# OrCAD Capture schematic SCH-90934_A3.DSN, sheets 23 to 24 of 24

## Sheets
23 C-16 IO EXPI/Miscs: size A2
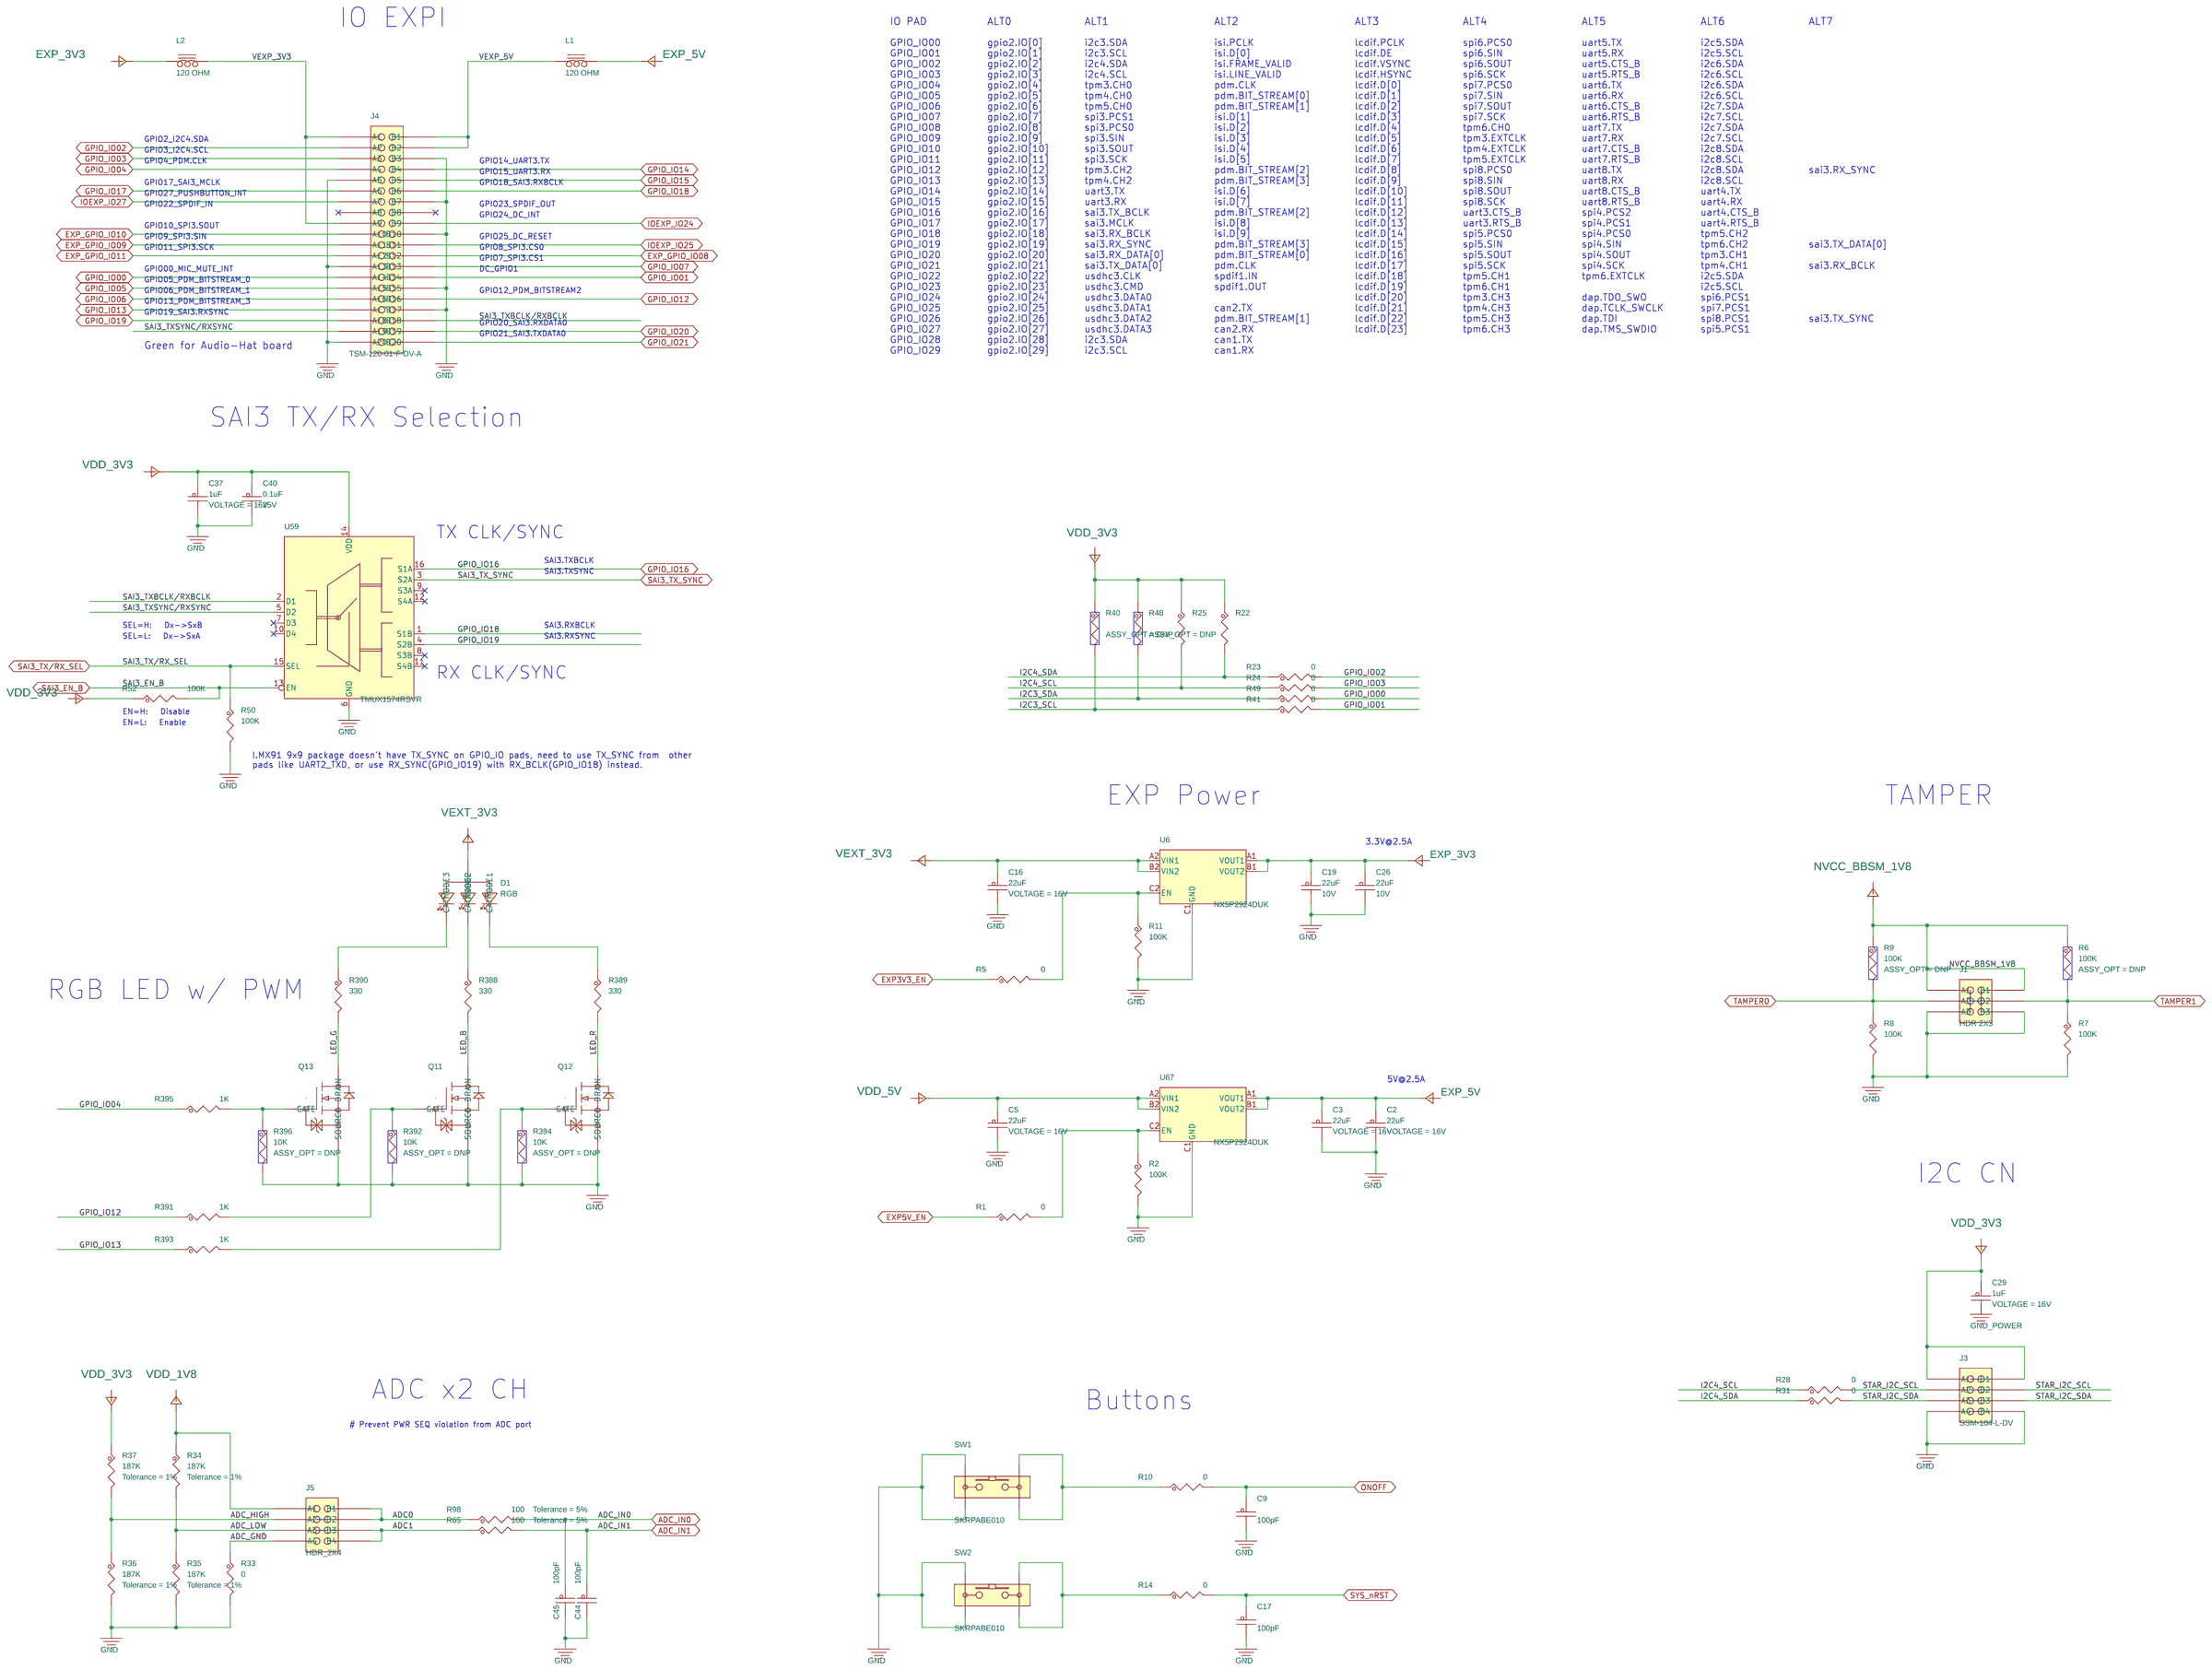
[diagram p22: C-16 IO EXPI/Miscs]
24 C-08 eMMC/MicroSD/QSPI: size C
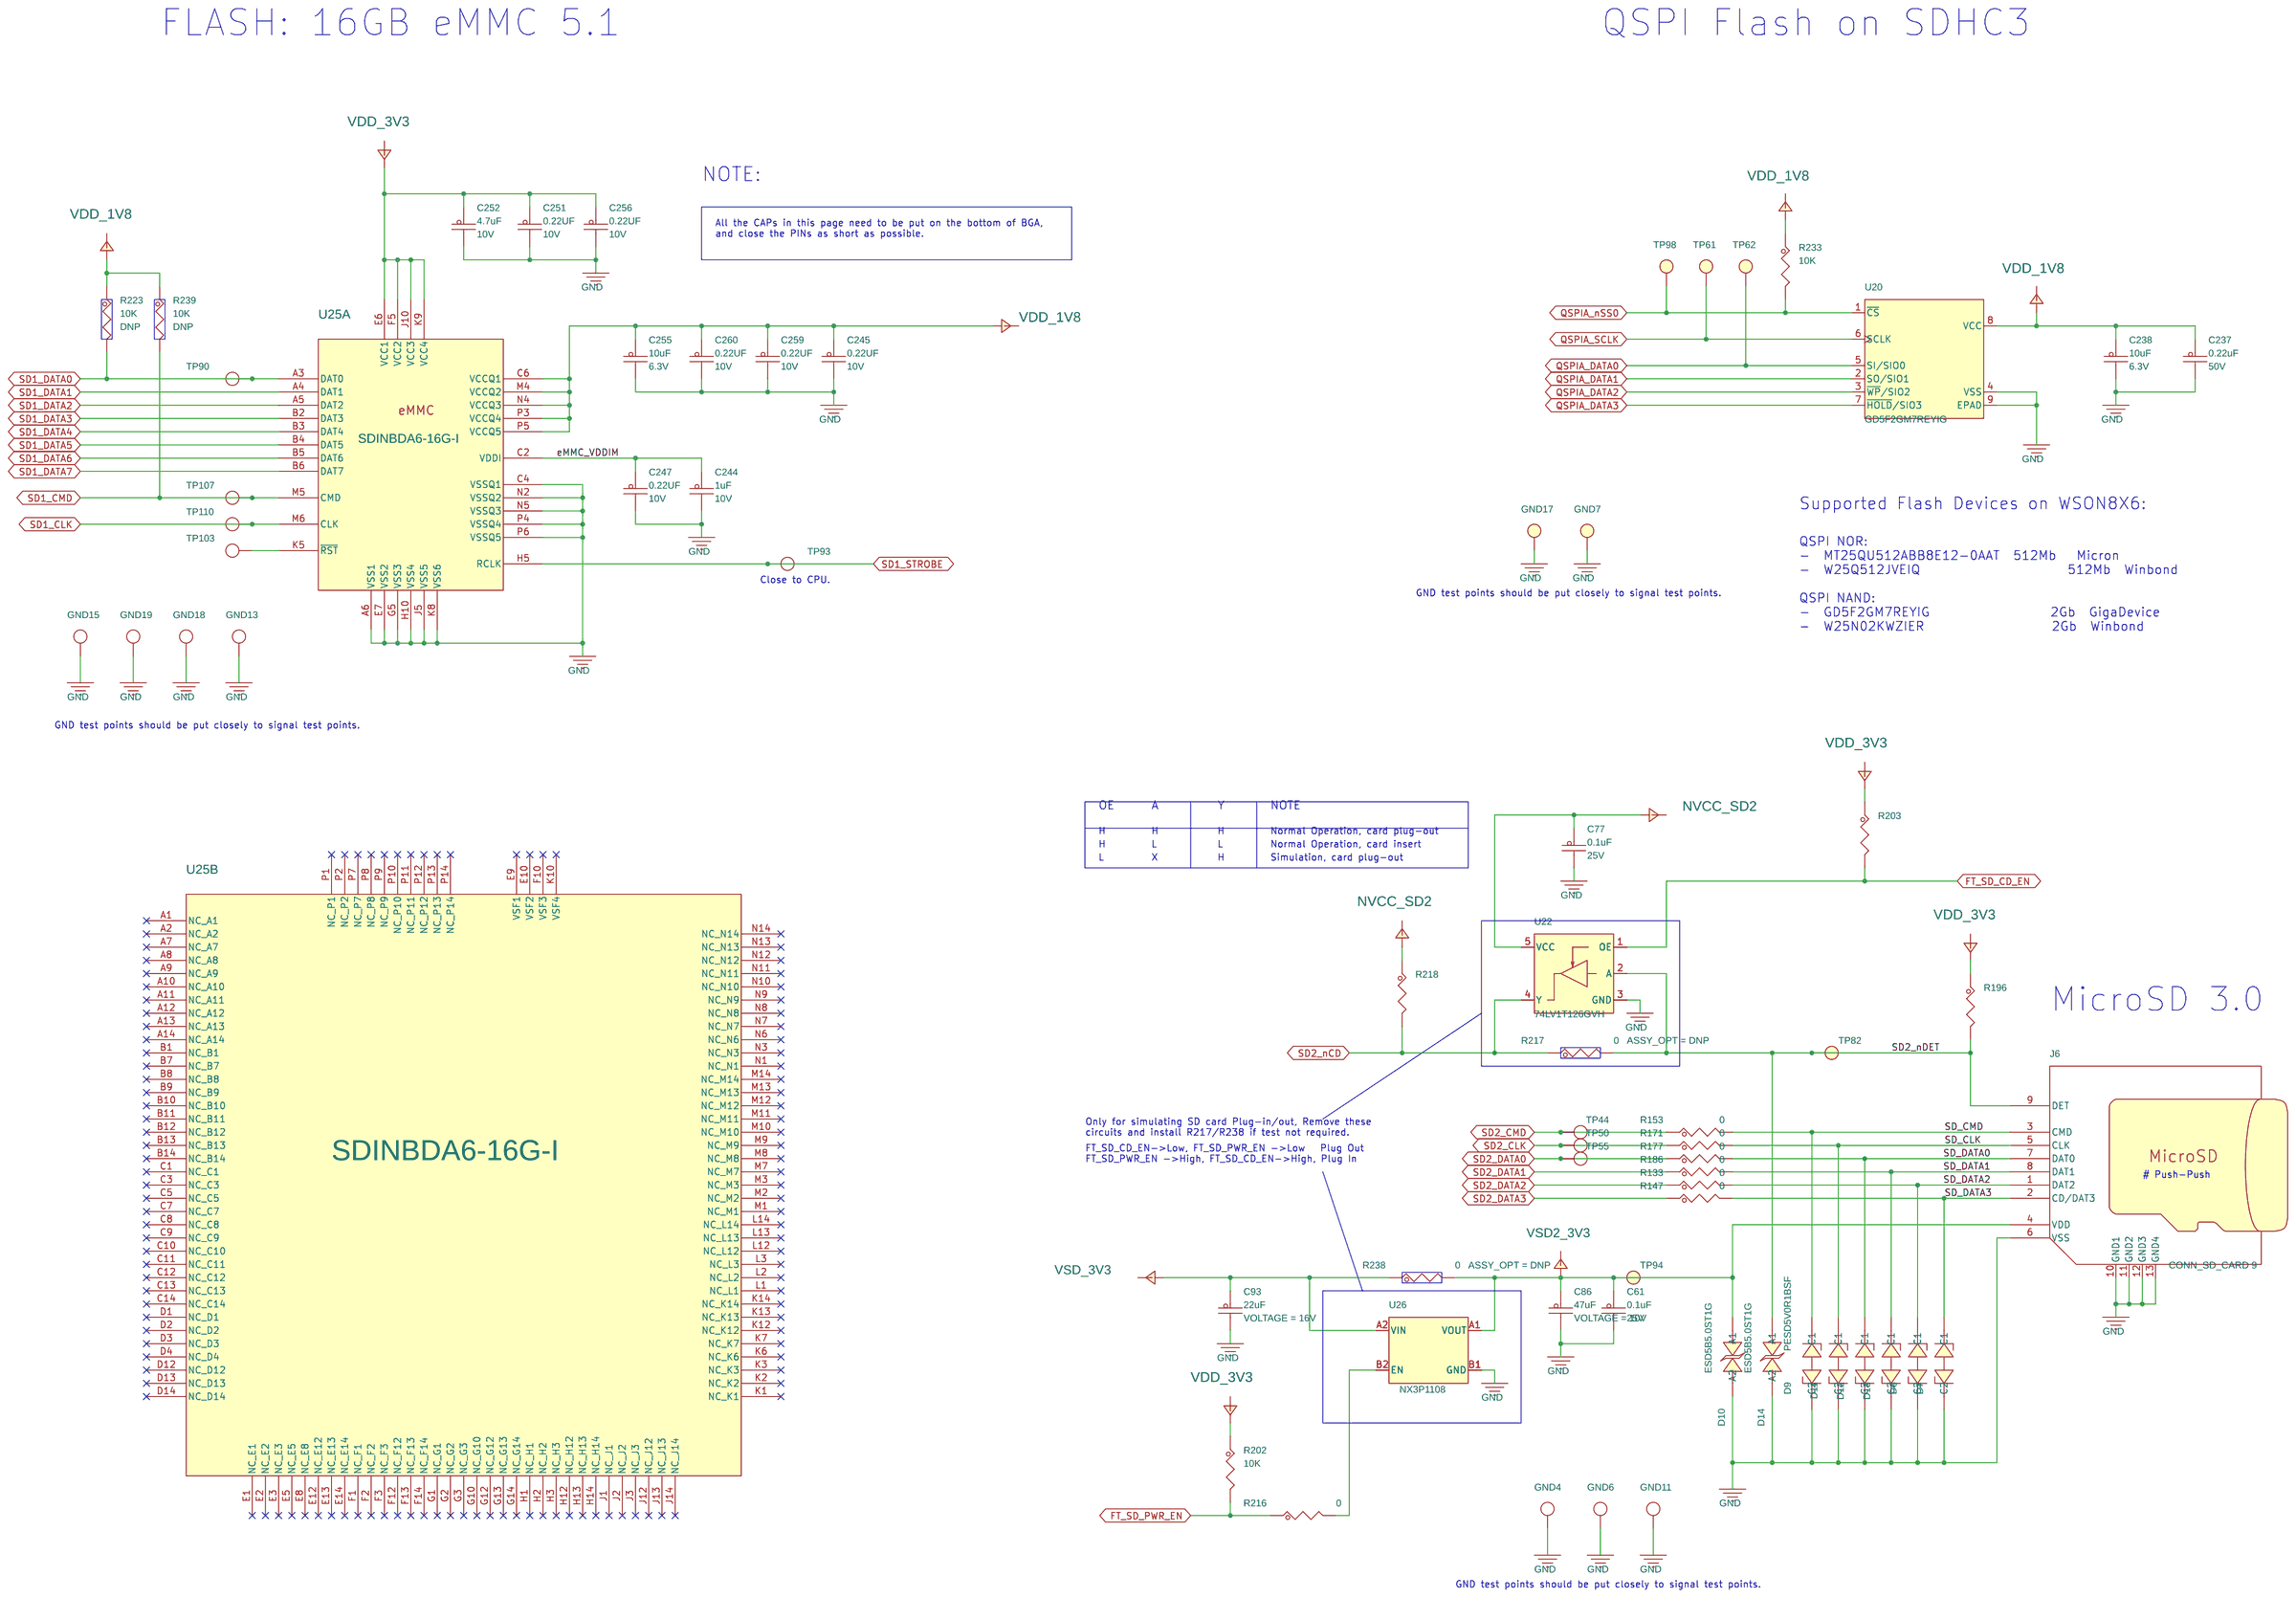
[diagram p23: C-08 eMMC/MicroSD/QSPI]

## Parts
sheet C-08 eMMC/MicroSD/QSPI
C61  0.1uF  [CC0402_25]
C77  0.1uF  [CC0402_25]
C86  47uF  [0805_CC]
C93  22uF  [CC0805_OV]
C237  0.22uF  [CC0402_25]
C238  10uF  [0402_cc_nsp]
C244  1uF  [0201_CC]
C245  0.22UF  [0201_CC]
C247  0.22UF  [0201_CC]
C251  0.22UF  [0201_CC]
C252  4.7uF  [cc0402_tol0p15]
C255  10uF  [0402_cc_nsp]
C256  0.22UF  [0201_CC]
C259  0.22UF  [0201_CC]
C260  0.22UF  [0201_CC]
D6  PESD5V0R1BSF  [dsn0603-2]
D7  PESD5V0R1BSF  [dsn0603-2]
D9  PESD5V0R1BSF  [dsn0603-2]
D10  ESD5B5.0ST1G  [diode2_sod523]
D11  PESD5V0R1BSF  [dsn0603-2]
D12  PESD5V0R1BSF  [dsn0603-2]
D13  PESD5V0R1BSF  [dsn0603-2]
D14  ESD5B5.0ST1G  [diode2_sod523]
GND4  TPAD_020  [tpad_020]
GND6  TPAD_020  [tpad_020]
GND7  TP_35MIL  [testpoint_35mil]
GND11  TPAD_020  [tpad_020]
GND13  TPAD_020  [tpad_020]
GND15  TPAD_020  [tpad_020]
GND17  TP_35MIL  [testpoint_35mil]
GND18  TPAD_020  [tpad_020]
GND19  TPAD_020  [tpad_020]
J6  CONN_SD_CARD 9  [con9_sdcard_1p1mm]
R133  0  [0402_CC]
R147  0  [0402_CC]
R153  0  [0402_CC]
R171  0  [0402_CC]
R177  0  [0402_CC]
R186  0  [0402_CC]
R196  10K  [0402_CC]
R202  10K  [0402_CC]
R203  10K  [0402_CC]
R216  0  [0402_CC]
R217  0  [0402_CC]
R218  10K  [0402_CC]
R223  10K  [0402_CC]
R233  10K  [0402_CC]
R238  0  [0402_CC]
R239  10K  [0402_CC]
TP44  TPAD_020  [tpad_020]
TP50  TPAD_020  [tpad_020]
TP55  TPAD_020  [tpad_020]
TP61  TP_35MIL  [testpoint_35mil]
TP62  TP_35MIL  [testpoint_35mil]
TP82  TP_35MIL  [testpoint_35mil]
TP90  TPAD_020  [tpad_020]
TP93  TPAD_020  [tpad_020]
TP94  TP_35MIL  [testpoint_35mil]
TP98  TP_35MIL  [testpoint_35mil]
TP103  TPAD_015  [TPAD_015]
TP107  TPAD_020  [tpad_020]
TP110  TPAD_020  [tpad_020]
U20  GD5F2GM7REYIG  [wson8_1p27_8x6mm_ep136x171]
U22  74LV1T126GVH  [sot753_5p_1p7x3p1mm]
U25  SDINBDA6-16G-I  [fbga153_0p5_11p5x13]  (sections A,B)
U26  NX3P1108  [wlcsp4_0p5_0p99x0P99]
sheet C-16 IO EXPI/Miscs
C2  22uF  [CC0805_OV]
C3  22uF  [CC0805_OV]
C5  22uF  [CC0805_OV]
C9  100pF  [CC0402_25]
C16  22uF  [CC0805_OV]
C17  100pF  [CC0402_25]
C19  22uF  [CC0603]
C26  22uF  [CC0603]
C29  1uF  [CC0402_25]
C37  1uF  [CC0402_25]
C40  0.1uF  [CC0402_25]
C44  100pF  [CC0402_25]
C45  100pF  [CC0402_25]
D1  RGB  [led4_3p4x3_sm]
J1  HDR 2X3  [hdr203_tmm_210h]
J3  SSM-104-L-DV  [con_2x4_skt_100_sm]
J4  TSM-120-01-F-DV-A  [hdr220_tsm_a_sm]
J5  HDR_2X4  [HDR204_TMM_SM]
L1  120 OHM  [IND_0603]
L2  120 OHM  [IND_0603]
Q11  NX3008NBKW,115  [sc70_3]
Q12  NX3008NBKW,115  [sc70_3]
Q13  NX3008NBKW,115  [sc70_3]
R1  0  [0402_CC]
R2  100K  [0402_CC]
R5  0  [0402_CC]
R6  100K  [0402_CC]
R7  100K  [0402_CC]
R8  100K  [0402_CC]
R9  100K  [0402_CC]
R10  0  [0402_CC]
R11  100K  [0402_CC]
R14  0  [0402_CC]
R22  2.2K  [0402_CC]
R23  0  [0402_CC]
R24  0  [0402_CC]
R25  2.2K  [0402_CC]
R28  0  [0402_CC]
R31  0  [0402_CC]
R33  0  [0402_CC]
R34  187K  [0402_CC]
R35  187K  [0402_CC]
R36  187K  [0402_CC]
R37  187K  [0402_CC]
R40  2.2K  [0402_CC]
R41  0  [0402_CC]
R48  2.2K  [0402_CC]
R49  0  [0402_CC]
R50  100K  [0402_CC]
R52  100K  [0402_CC]
R65  100  [RC0402_25]
R98  100  [RC0402_25]
R388  330  [RC0402_25]
R389  330  [RC0402_25]
R390  330  [RC0402_25]
R391  1K  [0402_CC]
R392  10K  [0402_CC]
R393  1K  [0402_CC]
R394  10K  [0402_CC]
R395  1K  [0402_CC]
R396  10K  [0402_CC]
SW1  SKRPABE010  [sw4_skrp]
SW2  SKRPABE010  [sw4_skrp]
U6  NX5P2924DUK  [wlcsp6_0p5_0p89x1p39]
U59  TMUX1574RSVR  [pqfn16_0p4_2p65x1p85]
U67  NX5P2924DUK  [wlcsp6_0p5_0p89x1p39]

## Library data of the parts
C40 C61 C77 = CAP_NP: CAP CER 0.1UF 25V 10% X5R 0402; AGILE_PN: 150-78633; CAD_APPROVED: Yes; FPLIST: CC0402_25,CC0402_HD,0402_CC,capc0402_l; HEIGHT: 0.55MM; MFG_NAME01: YAGEO AMERICA; MFG_PN01: CC0402KRX5R8BB104; Package Size: 0402; ROHS: Yes; Rated Voltage: 25V; Temp Range: -55C to +85C; Tolerance: 10%; VOLTAGE: 25V
C86 = CAP_NP: CAP CER 47uF 10V 20% X5R 0805; AGILE_PN: 150-78979; CAD_APPROVED: Yes; FPLIST: CC0805_OV,CC0805,0805_CC; HEIGHT: 1.45 MM; MFG_NAME01: TDK; MFG_PN01: C2012X5R1A476M125AC; ROHS: Yes; Rated Voltage: 10V; Temp Range: -55C to +85C; Tolerance: 20%; VOLTAGE: 10V
C2 C3 C5 C16 C93 = CAP_NP: CAP CER 22UF 16V 20% X5R 0805; 3D_Mechanical_Footprint_File: http://fcl.am.freescale.net/ALLEGRO/step/cc0805_ov.STEP; AGILE_PN: 150-81221; CAD_APPROVED: Yes; FPLIST: CC0805_OV,CC0805,0805_CC; HEIGHT: 1.45MM; MFG_NAME01: TDK Corporation; MFG_PN01: C2012X5R1C226M125AC; Package Size: 0805 (2012 Metric); ROHS: Yes; Rated Voltage: 16V; Temp Range: -55C to +85C; Tolerance: 20%; VOLTAGE: 16V
C237 = CAP_NP: CAP CER 0.22uF 50V 10% X5R 0402; AGILE_PN: 150-79999; CAD_APPROVED: Yes; FPLIST: CC0402_25,CC0402_HD,0402_CC; HEIGHT: 0.55MM; MFG_NAME01: TAIYO YUDEN; MFG_PN01: UMK105BJ224KV-F; Package Size: 0402; ROHS: Yes; Rated Voltage: 50V; Temp Range: -55C to +85C; Temp_Range: -55°C to +85°C; Tolerance: 10%; VOLTAGE: 50V
C238 C255 = CAP_NP: CAP CER 10UF 6.3V 20% X5R 0402; 3D_Mechanical_Footprint_File: cc0402_tol0p2; AGILE_PN: 150-79163; CAD_APPROVED: Yes; FPLIST: CC0402_25,CC0402_HD,0402_CC; HEIGHT: 0.7 MM; MFG_NAME01: SAMSUNG ELECTRO MECHANICS; MFG_PN01: CL05A106MQ5NUNC; ROHS: Yes; Rated Voltage: 6.3V; Temp Range: -55C to +85C; Tolerance: 20%; VOLTAGE: 6.3V
C244 = CAP_NP: CAP CER 1.0uF 10V 10% X5R 0201; AGILE_PN: 150-81088; CAD_APPROVED: Yes; FPLIST: CC0201,CC0201_HD,0201_CC,cc_0201_cir; HEIGHT: 0.35MM; MFG_NAME01: SAMSUNG ELECTRO MECHANICS; MFG_PN01: CL03A105KP3NSNC; Package Size: 0201 (0603 Metric); Package Type: SMD/SMT; ROHS: Yes; Rated Voltage: 10V; Temp Range: -55C to +85C; Tolerance: 10%; VOLTAGE: 10V
C245 C247 C251 C256 C259 C260 = CAP_NP: CAP CER 0.22UF 10V 20% X5R 0201; 3D_Mechanical_Footprint_File: http://fcl.am.freescale.net/ALLEGRO/step/cc0201.STEP; AGILE_PN: 150-78815; CAD_APPROVED: Yes; FPLIST: CC0201,CC0201_HD,0201_CC; HEIGHT: 0.33MM; MFG_NAME01: KYOCERA; MFG_PN01: 0201ZD224MAT2A; Package Size: 0201; ROHS: Yes; Rated Voltage: 10V; Temp Range: -55C to +85C; Tolerance: 20%; VOLTAGE: 10V
C252 = CAP_NP: CAP CER 4.7uF 10V 10% X5R 0402; AGILE_PN: 150-80044; CAD_APPROVED: Yes; FPLIST: cc0402_tol0p15,cc0402_tol0p15_ov,0402_cc_nsp; HEIGHT: 0.65MM; MFG_NAME01: SAMSUNG ELECTRO MECHANICS; MFG_PN01: CL05A475KP5NRNC; ROHS: Yes; Rated Voltage: 10V; Temp Range: -55C to +85C; Tolerance: 10%; VOLTAGE: 10V
D6 D7 D9 D11-D13 = DIODE_BIDIR: DIODE TVS 5VWM 9.2VC DSN0603-2; 3D_Mechanical_Footprint_File: http://fcl.am.freescale.net/ALLEGRO/step/dsn0603-2.STEP; AGILE_PN: 480-79664; CAD_APPROVED: Yes; HEIGHT: 0.32; MFG_NAME01: NEXPERIA; MFG_PN01: PESD5V0R1BSFYL
D10 D14 = DIODE_TVS_BIDIR: DIODE SUPPRESSOR 16A@30NS 5V@1UA SOD-523; 3D_Mechanical_Footprint_File: http://fcl.am.freescale.net/ALLEGRO/step/diode2_sod523.STEP; AGILE_PN: 480-76937; CAD_APPROVED: Yes; HEIGHT: 0.7; MFG_NAME01: ON SEMICONDUCTOR
GND4 GND6 GND11 GND13 GND15 GND18 GND19 TP44 TP50 TP55 TP90 TP93 TP107 TP110 = TESTLOOP: TEST POINT PAD 0.5MM DIA SMT, NO PART TO ORDER; AGILE_PN: 211-77484; ASSY_OPT: DNP; CAD_APPROVED: Yes; HEIGHT: 0.1MM; ROHS: Yes
GND7 GND17 TP61 TP62 TP82 TP94 TP98 = T_POINT_R: TEST POINT PAD .035 SMT, no part to order; AGILE_PN: 510-75618; ASSY_OPT: DNP; CAD_APPROVED: Yes; HEIGHT: 0.1MM; ROHS: Yes
J6 = CONN_MICRO_SDCARD: CON 9 SD CARD PUSH SMT 1.1MM SP 81H AU; AGILE_PN: 211-79878; CAD_APPROVED: Yes; HEIGHT: 2.05; MFG_NAME01: SHENZHEN ATOM TECHNOLOGY CO.,LTD; MFG_PN01: MR01A-01202; Package Type: SMT; ROHS: Yes
R1 R5 R10 R14 R23 R24 R28 R31 R33 R41 R49 R133 R147 R153 R171 R177 R186 R216 = RES: RES MF ZERO OHM 1/16W 5% 0402; AGILE_PN: 470-75394; CAD_APPROVED: Yes; FPLIST: RC0402_25,RC0402_HD,RC0402_X2,0402_CC; HEIGHT: 0.45; MFG_NAME01: YAGEO AMERICA; MFG_PN01: RC0402JR-070RL; ROHS: Yes; Temp Range: -55 to +155C; Tolerance: 5%; VOLTAGE: 1/16W
R196 R202 R203 R218 R233 = RES: RES MF 10K 1/16W 5% 0402; AGILE_PN: 470-75557; CAD_APPROVED: Yes; FPLIST: RC0402_25,RC0402_HD,0402_CC; HEIGHT: 0.4 MM; MFG_NAME01: VISHAY INTERTECHNOLOGY; MFG_PN01: CRCW040210K0JNED; ROHS: Yes; Tolerance: 5%
R217 R238 = RES: RES MF ZERO OHM 1/16W 5% 0402; AGILE_PN: 470-75394; ASSY_OPT: DNP; CAD_APPROVED: Yes; FPLIST: RC0402_25,RC0402_HD,RC0402_X2,0402_CC; HEIGHT: 0.45; MFG_NAME01: YAGEO AMERICA; MFG_PN01: RC0402JR-070RL; ROHS: Yes; Temp Range: -55 to +155C; Tolerance: 5%; VOLTAGE: 1/16W
R223 R239 R392 R394 R396 = RES: RES MF 10K 1/16W 5% 0402; AGILE_PN: 470-75557; ASSY_OPT: DNP; CAD_APPROVED: Yes; FPLIST: RC0402_25,RC0402_HD,0402_CC; HEIGHT: 0.4 MM; MFG_NAME01: VISHAY INTERTECHNOLOGY; MFG_PN01: CRCW040210K0JNED; ROHS: Yes; Tolerance: 5%
TP103 = TESTLOOP: TEST POINT PAD 15MIL DIA SMT, NO PART TO ORDER; AGILE_PN: 211-76645; ASSY_OPT: DNP; CAD_APPROVED: Yes; HEIGHT: 0.1MM; MFG_NAME01: NOTACOMPONENT; MFG_PN01: NOTACOMPONENT; ROHS: Yes
U20 = GD5F1GQ4RCYIG_WSON8: IC SPI NAND FLASH QUAD 2Gb 104MHz 1.7-2V WSON8; 3D_Mechanical_Footprint_File: http://fcl.am.freescale.net/ALLEGRO/step/wson8_1p27_8x6mm_ep136x171.step; AGILE_PN: 342-82716; CAD_APPROVED: Yes; HEIGHT: 0.85; MFG_NAME01: GIGA DEVICE SEMICONDUCTOR INC.; ROHS: Yes; Temp Range: -40C to +85C; VOLTAGE: 1.7-2V
U22 = 74LV1T126GVH: IC VXLTR 1BIT BUF DRV 1.6-5.5V SOT753; 3D_Mechanical_Footprint_File: http://fcl.am.freescale.net/ALLEGRO/step/sot753_5p_1p7x3p1mm.STEP; AGILE_PN: 312-83148; CAD_APPROVED: Yes; HEIGHT: 1.1; MFG_NAME01: Nexperia; Package Size: SC-74A-5; ROHS: Yes; Temp Range: -40°C to +125°C; VOLTAGE: 1.6-5.5V
U25 = SDINBDA6_32G_I_VFBGA_153P: IC MEM NAND FLASH 16GB MMC 5.1 CTLR 2.7-3.6V FBGA153; 3D_Mechanical_Footprint_File: http://fcl.am.freescale.net/ALLEGRO/step/fbga153_0p5_11p5x13.STEP; AGILE_PN: 342-00870; CAD_APPROVED: Yes; HEIGHT: 1; MFG_NAME01: SANDISK CORPORATION; ROHS: Yes; Temp Range: -25°C to 85°C
U26 = NX3P1108_4P: IC LOAD SW 1.5A 0.9-3.6V WLCSP4; 3D_Mechanical_Footprint_File: http://fcl.am.freescale.net/ALLEGRO/step/wlcsp4_0p5_0p99x0P99.STEP; AGILE_PN: 315-81596; CAD_APPROVED: Yes; HEIGHT: 0.59; MFG_NAME01: NXP SEMICONDUCTOR; MFG_PN01: NX3P1108UKZ; ROHS: Yes; Temp Range: -40C to +85C; VOLTAGE: 0.9-3.6V
C9 C17 C44 C45 = CAP_NP: CAP CER 100PF 50V 5% C0G 0402; AGILE_PN: 150-79170; CAD_APPROVED: Yes; FPLIST: CC0402_25,CC0402_HD,0402_CC,capc0402_l; HEIGHT: 0.55MM; MFG_NAME01: AVX; MFG_PN01: 04025A101JAT2A; ROHS: Yes; Rated Voltage: 50V; Temp Range: -55C to +125C; Tolerance: 5%; VOLTAGE: 50V
C19 C26 = CAP_NP: CAP CER 22uF 10V 20% X5R 0603; AGILE_PN: 150-79530; CAD_APPROVED: Yes; FPLIST: CC0603_OV,CC0603,0603_cc_tol; HEIGHT: 1MM; MFG_NAME01: SAMSUNG; MFG_PN01: CL10A226MP7LUNC; Package Size: 0603; ROHS: Yes; Rated Voltage: 10V; SIGNAL_MODEL: DEFAULT_CAPACITOR_2.2e+07pF_2_1; Temp Range: -55C to +85C; Tolerance: 20%; VOLTAGE: 10V; WVDC: 6.3V
C29 C37 = CAP_NP: CAP CER 1uF 16V 10% X5R 0402; AGILE_PN: 150-78973; CAD_APPROVED: Yes; FPLIST: CC0402_25,CC0402_HD,0402_CC,capc0402_l; HEIGHT: 0.55 MM; MFG_NAME01: TDK; MFG_PN01: C1005X5R1C105K; ROHS: Yes; Rated Voltage: 16V; SIGNAL_MODEL: DEFAULT_CAPACITOR_1e+06pF_2_1; TOL: 10%; Temp Range: -55C to +85C; Tolerance: 10%; VOLTAGE: 16V; voltage rating: 16V
D1 = LED_GPLY6900: LED RGB MULTI 20MA SMT; AGILE_PN: 370-76731; CAD_APPROVED: Yes; HEIGHT: 2.04; MFG_NAME01: EVERLIGHT INTERNATIONAL CORPORATION; MFG_PN01: 67-03A/R6GHBHW-A01/2T/MS; Rated Voltage: 1.7-3.7V; VOLTAGE: 1.7-3.7V
J1 = CONN_HDR_3X2: HDR 2X3 TH 2MM CTR 217H AU 110L; 3D_Mechanical_Footprint_File: http://fcl.am.freescale.net/ALLEGRO/step/hdr203_tmm_210h.STEP; AGILE_PN: 210-77094; CAD_APPROVED: Yes; FPLIST: hdr203_tmm_210h,hdr203_tmm; HEIGHT: 5.33; MFG_NAME01: SAMTEC; MFG_PN01: TMM-103-02-G-D; ROHS: Yes
J3 = CONN_HDR_4X2: CON 2X4 SKT SMT 2.54MM CTR 300H AU; 3D_Mechanical_Footprint_File: http://fcl.am.freescale.net/ALLEGRO/step/con_2x4_skt_100_sm.STEP; AGILE_PN: 211-79467; CAD_APPROVED: Yes; HEIGHT: 7.62; MFG_NAME01: SAMTEC; ROHS: Yes
J4 = CONN_HDR_20X2: HDR 2X20 SMT 2.54MM CTR 395H AU; 3D_Mechanical_Footprint_File: http://fcl.am.freescale.net/ALLEGRO/step/hdr220_tsm_a_sm.step; AGILE_PN: 211-80156; CAD_APPROVED: Yes; HEIGHT: 10.03; MFG_NAME01: SAMTEC; ROHS: Yes; Temp Range: -55°C ~ 125°C
J5 = CONN_HDR_4X2: HDR 2X4 SMT 78.7MIL CTR 235H AU LOPRO; 3D_Mechanical_Footprint_File: http://fcl.am.freescale.net/ALLEGRO/step/hdr204_tmm_sm.STEP; AGILE_PN: 211-75114; CAD_APPROVED: Yes; HEIGHT: 5.97; MFG_NAME01: SAMTEC; MFG_PN01: TMM-104-01-S-D-SM; Package Size: SMD-8; Package Type: SMD; ROHS: Yes; Temp Range: -55°C to +125°C
L1 L2 = BEAD_0: IND FER BEAD 120OHM@100MHZ 2A 25% 0603; AGILE_PN: 180-78419; CAD_APPROVED: Yes; FPLIST: IND_0603,0603_CC; HEIGHT: 0.95; MFG_NAME01: MURATA; MFG_PN01: BLM18PG121SN1D; ROHS: Yes
Q11-Q13 = NX3008NBKW_SOT323: TRAN NMOS SW 30V 350mA AEC-Q101 SC-70; 3D_Mechanical_Footprint_File: http://fcl.am.freescale.net/ALLEGRO/step/sc70_3.STEP; AGILE_PN: 480-79736; CAD_APPROVED: Yes; HEIGHT: 1.1; MFG_NAME01: NEXPERIA; ROHS: Yes
R2 R7 R8 R11 R50 R52 = RES: RES MF 100K 1/16W 5% 0402; AGILE_PN: 470-75597; CAD_APPROVED: Yes; FPLIST: RC0402_25,RC0402_HD,0402_CC; HEIGHT: 0.40 MM; MFG_NAME01: VENKEL COMPANY; MFG_PN01: CR0402-16W-104JT; ROHS: Yes; Temp Range: -55C to +155C; Temp_Range: -55C to +155C; Tolerance: 5%; VOLTAGE: 50V
R6 R9 = RES: RES MF 100K 1/16W 5% 0402; AGILE_PN: 470-75597; ASSY_OPT: DNP; CAD_APPROVED: Yes; FPLIST: RC0402_25,RC0402_HD,0402_CC; HEIGHT: 0.40 MM; MFG_NAME01: VENKEL COMPANY; MFG_PN01: CR0402-16W-104JT; ROHS: Yes; Temp Range: -55C to +155C; Temp_Range: -55C to +155C; Tolerance: 5%; VOLTAGE: 50V
R22 R25 = RES: RES MF 2.2K 1/16W 5% 0402; AGILE_PN: 470-76602; CAD_APPROVED: Yes; FPLIST: RC0402_25,RC0402_HD,0402_CC; HEIGHT: 0.4 MM; MFG_NAME01: YAGEO AMERICA; MFG_PN01: RC0402JR-072K2L; RATING: 1/16W; ROHS: Yes; Tolerance: 5%
R34-R37 = RES: RES MF 187K 1/16W 1% 0402; AGILE_PN: 470-31090; CAD_APPROVED: Yes; FPLIST: RC0402_25,RC0402_HD,0402_CC; HEIGHT: 0.40 MM; MFG_NAME01: WALSIN TECHNOLOGY CORP.; MFG_PN01: WR04X1873FTL; ROHS: Yes; Temp Range: -55C to +155C; Temp_Range: -55C to +155C; Tolerance: 1%; VOLTAGE: 50V
R40 R48 = RES: RES MF 2.2K 1/16W 5% 0402; AGILE_PN: 470-76602; ASSY_OPT: DNP; CAD_APPROVED: Yes; FPLIST: RC0402_25,RC0402_HD,0402_CC; HEIGHT: 0.4 MM; MFG_NAME01: YAGEO AMERICA; MFG_PN01: RC0402JR-072K2L; RATING: 1/16W; ROHS: Yes; Tolerance: 5%
R65 R98 = RES: RES MF 100 OHM 1/16W 5% 0402; AGILE_PN: 470-82142; CAD_APPROVED: Yes; FPLIST: RC0402_25,RC0402_HD,RC0402_X2,0402_CC; HEIGHT: 0.45MM; MFG_NAME01: SMEC; MFG_PN01: RC73L2Z101JTF; ROHS: Yes; Temp Range: -55°C to +175°C; Tolerance: 5%
R388-R390 = RES: RES MF 330 OHM 1/16W 5% 0402; AGILE_PN: 470-82124; CAD_APPROVED: Yes; FPLIST: RC0402_25,RC0402_HD,0402_CC; HEIGHT: 0.4MM; MFG_NAME01: NIC COMPONENTS CORP; MFG_PN01: NRCL04J331TRF; ROHS: Yes; Temp Range: -55 ~ +155; Tolerance: 5%
R391 R393 R395 = RES: RES MF 1.0K 1/16W 5% 0402; AGILE_PN: 470-75555; CAD_APPROVED: Yes; FPLIST: RC0402_25,RC0402_HD,RC0402_X2,0402_CC,CAPC0402_L; HEIGHT: 0.41mm; MFG_NAME01: VISHAY INTERTECHNOLOGY; MFG_PN01: CRCW04021K00JNED; ROHS: Yes; Tolerance: 5%
SW1 SW2 = SW_TC_SPST_4P: SW SPST PB SMT 16V 20MA; 3D_Mechanical_Footprint_File: http://fcl.am.freescale.net/ALLEGRO/step/sw4_skrp.step; AGILE_PN: 510-75638; CAD_APPROVED: Yes; HEIGHT: 2.5MM; MFG_NAME01: ALPS ELECTRIC (USA) INC.; ROHS: Yes
U6 U67 = NX5P2924DUK_WLCSP6: IC PWR SW LOGIC CONTROLED 0.8-5.5V 2.5A WLCSP6; 3D_Mechanical_Footprint_File: http://fcl.am.freescale.net/ALLEGRO/step/wlcsp6_0p5_0p89x1p39.STEP; AGILE_PN: 315-83992; CAD_APPROVED: Yes; HEIGHT: 0.5; MFG_NAME01: NXP SEMICONDUCTOR; ROHS: Yes; Temp Range: -40  °C  +85 °C; VOLTAGE: 0.8-5.5V
U59 = TMUX1574RSVR_A: IC MUX SW SPDT 1.8V UQFN16; 3D_Mechanical_Footprint_File: http://fcl.am.freescale.net/ALLEGRO/step/pqfn16_0p4_2p65x1p85.STEP; AGILE_PN: 312-82341; CAD_APPROVED: Yes; HEIGHT: 0.55; MFG_NAME01: TEXAS INSTRUMENTS; ROHS: Yes; Temp Range: -40C to +125C; VOLTAGE: 1.5-5.5V

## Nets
GND: C2.2 C3.2 C5.2 C9.2 C16.2 C17.2 C19.2 C26.2 C29.2 C37.2 C40.2 C44.2 C45.2 C61.2 C77.2 C86.2 C93.2 C237.2 C238.2 C244.2 C245.2 C247.2 C251.2 C252.2 C255.2 C256.2 C259.2 C260.2 D6.2(C2) D7.2(C2) D9.2(C2) D10.2(A2) D11.2(C2) D12.2(C2) D13.2(C2) D14.2(A2) GND4.1(Pin1) GND6.1(Pin1) GND7.1(TP) GND11.1(Pin1) GND13.1(Pin1) GND15.1(Pin1) GND17.1(TP) GND18.1(Pin1) GND19.1(Pin1) J1.5(A3) J1.6(B3) J3.7(A4) J3.8(B4) J4.6(B3) J4.9(A5) J4.14(B7) J4.20(B10) J4.25(A13) J4.30(B15) J4.34(B17) J4.39(A20) J6.6(VSS) J6.10(GND1) J6.11(GND2) J6.12(GND3) J6.13(GND4) Q11.2(SOURCE) Q12.2(SOURCE) Q13.2(SOURCE) R2.2 R7.2 R8.2 R11.2 R33.2 R35.2 R36.2 R50.2 R392.2 R394.2 R396.2 SW1.1 SW1.2 SW2.1 SW2.2 U6.C1(GND) U20.4(VSS) U20.9(EPAD) U22.3(GND) U25.A6(VSS1) U25.C4(VSSQ1) U25.E7(VSS2) U25.G5(VSS3) U25.H10(VSS4) U25.J5(VSS5) U25.K8(VSS6) U25.N2(VSSQ2) U25.N5(VSSQ3) U25.P4(VSSQ4) U25.P6(VSSQ5) U26.B1(GND) U59.6(GND) U67.C1(GND) ; also on sheet 1 2 3 7 8 9 10 11 12 13 17 18 19 20 21 22
VDD_1V8: C237.1 C238.1 C245.1 C255.1 C259.1 C260.1 J5.1(A1) R34.1 R223.1 R233.1 R239.1 U20.8(VCC) U25.C6(VCCQ1) U25.M4(VCCQ2) U25.N4(VCCQ3) U25.P3(VCCQ4) U25.P5(VCCQ5) ; also on sheet 2 7 10 11 19 22
VDD_3V3: C29.1 C37.1 C40.1 C251.1 C252.1 C256.1 J3.1(A1) J3.2(B1) R22.1 R25.1 R37.1 R40.1 R48.1 R52.1 R196.1 R202.1 R203.1 U25.E6(VCC1) U25.F5(VCC2) U25.J10(VCC3) U25.K9(VCC4) U59.14(VDD) ; also on sheet 1 2 7 8 9 10 11 12 13 19 20 21 22
VDD_5V: C5.1 U67.A2(VIN1) U67.B2(VIN2) ; also on sheet 11 12 21
ADC0: J5.2(B1) J5.4(B2) R98.1
ADC1: J5.6(B3) J5.8(B4) R65.1
ADC_GND: J5.7(A4) R33.1
ADC_HIGH: J5.3(A2) R36.1 R37.2
ADC_IN0: C45.1 R98.2 ; also on sheet 3
ADC_IN1: C44.1 R65.2 ; also on sheet 3
ADC_LOW: J5.5(A3) R34.2 R35.1
eMMC_VDDIM: C244.1 C247.1 U25.C2(VDDI)
EXP3V3_EN: R5.1 ; also on sheet 13
EXP5V_EN: R1.1 ; also on sheet 13
EXP_3V3: C19.1 C26.1 L2.1 U6.A1(VOUT1) U6.B1(VOUT2)
EXP_5V: C2.1 C3.1 L1.2 U67.A1(VOUT1) U67.B1(VOUT2)
EXP_GPIO_IO08: J4.24(B12) ; also on sheet 13
EXP_GPIO_IO09: J4.21(A11) ; also on sheet 13
EXP_GPIO_IO10: J4.19(A10) ; also on sheet 13
EXP_GPIO_IO11: J4.23(A12) ; also on sheet 13
FT_SD_CD_EN: R203.2 U22.1(OE) ; also on sheet 7
FT_SD_PWR_EN: R202.2 R216.1 ; also on sheet 7
GPIO_IO00: J4.27(A14) R49.2 ; also on sheet 20
GPIO_IO01: J4.28(B14) R41.2 ; also on sheet 20
GPIO_IO02: J4.3(A2) R23.2 ; also on sheet 20
GPIO_IO03: J4.5(A3) R24.2 ; also on sheet 20
GPIO_IO04: J4.7(A4) R395.1 ; also on sheet 20
GPIO_IO05: J4.29(A15) ; also on sheet 20
GPIO_IO06: J4.31(A16) ; also on sheet 20
GPIO_IO07: J4.26(B13) ; also on sheet 20
GPIO_IO12: J4.32(B16) R391.1 ; also on sheet 20
GPIO_IO13: J4.33(A17) R393.1 ; also on sheet 20
GPIO_IO14: J4.8(B4) ; also on sheet 20
GPIO_IO15: J4.10(B5) ; also on sheet 20
GPIO_IO16: U59.16(S1A) ; also on sheet 20
GPIO_IO17: J4.11(A6) ; also on sheet 20
GPIO_IO18: J4.12(B6) U59.1(S1B) ; also on sheet 20
GPIO_IO19: J4.35(A18) U59.4(S2B) ; also on sheet 20
GPIO_IO20: J4.38(B19) ; also on sheet 20
GPIO_IO21: J4.40(B20) ; also on sheet 20
I2C3_SCL: R40.2 R41.1
I2C3_SDA: R48.2 R49.1
I2C4_SCL: R24.1 R25.2 R28.1
I2C4_SDA: R22.2 R23.1 R31.1
IOEXP_IO24: J4.18(B9) ; also on sheet 13
IOEXP_IO25: J4.22(B11) ; also on sheet 13
IOEXP_IO27: J4.13(A7) ; also on sheet 13
LED_B: Q11.3(DRAIN) R388.2
LED_G: Q13.3(DRAIN) R390.2
LED_R: Q12.3(DRAIN) R389.2
NVCC_BBSM_1V8: J1.1(A1) J1.2(B1) R6.1 R9.1 ; also on sheet 2 3 17
NVCC_SD2: C77.1 R218.1 U22.5(VCC) ; also on sheet 2 17 20
ONOFF: C9.1 R10.2 ; also on sheet 3 7
QSPIA_DATA0: TP62.1(TP) U20.5(SI/SIO0) ; also on sheet 13
QSPIA_DATA1: U20.2(SO/SIO1) ; also on sheet 13
QSPIA_DATA2: U20.3(~{WP}/SIO2) ; also on sheet 13
QSPIA_DATA3: U20.7(~{HOLD}/SIO3) ; also on sheet 13
QSPIA_nSS0: R233.2 TP98.1(TP) U20.1(~{CS}) ; also on sheet 13
QSPIA_SCLK: TP61.1(TP) U20.6(SCLK) ; also on sheet 13
SAI3_EN_B: R52.2 U59.13(EN) ; also on sheet 13
SAI3_TX/RX_SEL: R50.1 U59.15(SEL) ; also on sheet 13
SAI3_TX_SYNC: U59.3(S2A) ; also on sheet 1 20
SAI3_TXBCLK/RXBCLK: J4.36(B18) U59.2(D1)
SAI3_TXSYNC/RXSYNC: J4.37(A19) U59.5(D2)
SD1_CLK: TP110.1(Pin1) U25.M6(CLK) ; also on sheet 20
SD1_CMD: R239.2 TP107.1(Pin1) U25.M5(CMD) ; also on sheet 20
SD1_DATA0: R223.2 TP90.1(Pin1) U25.A3(DAT0) ; also on sheet 20
SD1_DATA1: U25.A4(DAT1) ; also on sheet 20
SD1_DATA2: U25.A5(DAT2) ; also on sheet 20
SD1_DATA3: U25.B2(DAT3) ; also on sheet 20
SD1_DATA4: U25.B3(DAT4) ; also on sheet 20
SD1_DATA5: U25.B4(DAT5) ; also on sheet 20
SD1_DATA6: U25.B5(DAT6) ; also on sheet 20
SD1_DATA7: U25.B6(DAT7) ; also on sheet 20
SD1_STROBE: TP93.1(Pin1) U25.H5(RCLK) ; also on sheet 20
SD2_CLK: R171.1 TP50.1(Pin1) ; also on sheet 20
SD2_CMD: R153.1 TP44.1(Pin1) ; also on sheet 20
SD2_DATA0: R177.1 TP55.1(Pin1) ; also on sheet 20
SD2_DATA1: R186.1 ; also on sheet 20
SD2_DATA2: R133.1 ; also on sheet 20
SD2_DATA3: R147.1 ; also on sheet 20
SD2_nCD: R217.1 R218.2 U22.4(Y) ; also on sheet 20
SD2_nDET: D14.1(A1) J6.9(DET) R196.2 R217.2 TP82.1(TP) U22.2(A)
SD_CLK: D11.1(C1) J6.5(CLK) R171.2
SD_CMD: D9.1(C1) J6.3(CMD) R153.2
SD_DATA0: D12.1(C1) J6.7(DAT0) R177.2
SD_DATA1: D13.1(C1) J6.8(DAT1) R186.2
SD_DATA2: D6.1(C1) J6.1(DAT2) R133.2
SD_DATA3: D7.1(C1) J6.2(CD/DAT3) R147.2
STAR_I2C_SCL: J3.3(A2) J3.4(B2) R28.2
STAR_I2C_SDA: J3.5(A3) J3.6(B3) R31.2
SYS_nRST: C17.1 R14.2 ; also on sheet 7 19
TAMPER0: J1.3(A2) R8.1 R9.2 ; also on sheet 3
TAMPER1: J1.4(B2) R6.2 R7.1 ; also on sheet 3
VEXP_3V3: J4.1(A1) J4.17(A9) L2.2
VEXP_5V: J4.2(B1) J4.4(B2) L1.1
VEXT_3V3: C16.1 D1.2(ANODE) U6.A2(VIN1) U6.B2(VIN2) ; also on sheet 22
VSD2_3V3: C61.1 C86.1 D10.1(A1) J6.4(VDD) R238.2 TP94.1(TP) U26.A1(VOUT)
VSD_3V3: C93.1 R238.1 U26.A2(VIN) ; also on sheet 19
N117433736: TP103.1(Pin1) U25.K5(~{RST})
N117434649: R216.2 U26.B2(EN)
N117462626: R5.2 R11.1 U6.C2(EN)
N117462672: D1.4(CATHODE3) R390.1
N117462674: D1.3(CATHODE2) R388.1
N117462676: D1.1(CATHODE1) R389.1
N117462986: Q13.1(GATE) R395.2 R396.1
N117462992: Q11.1(GATE) R391.2 R392.1
N117463000: Q12.1(GATE) R393.2 R394.1
N117463075: R1.2 R2.1 U67.C2(EN)
N117463350: R10.1 SW1.3 SW1.4
N117463581: R14.1 SW2.3 SW2.4

Not connected (* = marked no-connect by the designer): J4 15(A8)* 16(B8)*; U25 A1(NC)* A2(NC)* A7(NC)* A8(NC)* A9(NC)* A10(NC)* A11(NC)* A12(NC)* A13(NC)* A14(NC)* B1(NC)* B7(NC)* B8(NC)* B9(NC)* B10(NC)* B11(NC)* B12(NC)* B13(NC)* B14(NC)* C1(NC)* C3(NC)* C5(NC)* C7(NC)* C8(NC)* C9(NC)* C10(NC)* C11(NC)* C12(NC)* C13(NC)* C14(NC)* D1(NC)* D2(NC)* D3(NC)* D4(NC)* D12(NC)* D13(NC)* D14(NC)* E1(NC)* E2(NC)* E3(NC)* E5(NC)* E8(NC)* E9(VSF1)* E10(VSF2)* E12(NC)* E13(NC)* E14(NC)* F1(NC)* F2(NC)* F3(NC)* F10(VSF3)* F12(NC)* F13(NC)* F14(NC)* G1(NC)* G2(NC)* G3(NC)* G10(NC)* G12(NC)* G13(NC)* G14(NC)* H1(NC)* H2(NC)* H3(NC)* H12(NC)* H13(NC)* H14(NC)* J1(NC)* J2(NC)* J3(NC)* J12(NC)* J13(NC)* J14(NC)* K1(NC)* K2(NC)* K3(NC)* K6(NC)* K7(NC)* K10(VSF4)* K12(NC)* K13(NC)* K14(NC)* L1(NC)* L2(NC)* L3(NC)* L12(NC)* L13(NC)* L14(NC)* M1(NC)* M2(NC)* M3(NC)* M7(NC)* M8(NC)* M9(NC)* M10(NC)* M11(NC)* M12(NC)* M13(NC)* M14(NC)* N1(NC)* N3(NC)* N6(NC)* N7(NC)* N8(NC)* N9(NC)* N10(NC)* N11(NC)* N12(NC)* N13(NC)* N14(NC)* P1(NC)* P2(NC)* P7(NC)* P8(NC)* P9(NC)* P10(NC)* P11(NC)* P12(NC)* P13(NC)* P14(NC)*; U59 7(D3)* 8(S3B)* 9(S3A)* 10(D4)* 11(S4B)* 12(S4A)*

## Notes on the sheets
sheet 23
- IO EXPI
- IO PAD
- ALT0
- ALT1
- ALT2
- ALT3
- ALT4
- ALT5
- ALT6
- ALT7
- GPIO_IO00
  GPIO_IO01
  GPIO_IO02
  GPIO_IO03
  GPIO_IO04
  GPIO_IO05
  GPIO_IO06
  GPIO_IO07
  GPIO_IO08
  GPIO_IO09
  GPIO_IO10
  GPIO_IO11
  GPIO_IO12
  GPIO_IO13
  GPIO_IO14
  GPIO_IO15
  GPIO_IO16
  GPIO_IO17
  GPIO_IO18
  GPIO_IO19
  GPIO_IO20
  GPIO_IO21
  GPIO_IO22
  GPIO_IO23
  GPIO_IO24
  GPIO_IO25
  GPIO_IO26
  GPIO_IO27
  GPIO_IO28
  GPIO_IO29
- gpio2.IO[0]
  gpio2.IO[1]
  gpio2.IO[2]
  gpio2.IO[3]
  gpio2.IO[4]
  gpio2.IO[5]
  gpio2.IO[6]
  gpio2.IO[7]
  gpio2.IO[8]
  gpio2.IO[9]
  gpio2.IO[10]
  gpio2.IO[11]
  gpio2.IO[12]
  gpio2.IO[13]
  gpio2.IO[14]
  gpio2.IO[15]
  gpio2.IO[16]
  gpio2.IO[17]
  gpio2.IO[18]
  gpio2.IO[19]
  gpio2.IO[20]
  gpio2.IO[21]
  gpio2.IO[22]
  gpio2.IO[23]
  gpio2.IO[24]
  gpio2.IO[25]
  gpio2.IO[26]
  gpio2.IO[27]
  gpio2.IO[28]
  gpio2.IO[29]
- i2c3.SDA
  i2c3.SCL
  i2c4.SDA
  i2c4.SCL
  tpm3.CH0
  tpm4.CH0
  tpm5.CH0
  spi3.PCS1
  spi3.PCS0
  spi3.SIN
  spi3.SOUT
  spi3.SCK
  tpm3.CH2
  tpm4.CH2
  uart3.TX
  uart3.RX
  sai3.TX_BCLK
  sai3.MCLK
  sai3.RX_BCLK
  sai3.RX_SYNC
  sai3.RX_DATA[0]
  sai3.TX_DATA[0]
  usdhc3.CLK
  usdhc3.CMD
  usdhc3.DATA0
  usdhc3.DATA1
  usdhc3.DATA2
  usdhc3.DATA3
  i2c3.SDA
  i2c3.SCL
- isi.PCLK
  isi.D[0]
  isi.FRAME_VALID
  isi.LINE_VALID
  pdm.CLK
  pdm.BIT_STREAM[0]
  pdm.BIT_STREAM[1]
  isi.D[1]
  isi.D[2]
  isi.D[3]
  isi.D[4]
  isi.D[5]
  pdm.BIT_STREAM[2]
  pdm.BIT_STREAM[3]
  isi.D[6]
  isi.D[7]
  pdm.BIT_STREAM[2]
  isi.D[8]
  isi.D[9]
  pdm.BIT_STREAM[3]
  pdm.BIT_STREAM[0]
  pdm.CLK
  spdif1.IN
  spdif1.OUT
  can2.TX
  pdm.BIT_STREAM[1]
  can2.RX
  can1.TX
  can1.RX
- lcdif.PCLK
  lcdif.DE
  lcdif.VSYNC
  lcdif.HSYNC
  lcdif.D[0]
  lcdif.D[1]
  lcdif.D[2]
  lcdif.D[3]
  lcdif.D[4]
  lcdif.D[5]
  lcdif.D[6]
  lcdif.D[7]
  lcdif.D[8]
  lcdif.D[9]
  lcdif.D[10]
  lcdif.D[11]
  lcdif.D[12]
  lcdif.D[13]
  lcdif.D[14]
  lcdif.D[15]
  lcdif.D[16]
  lcdif.D[17]
  lcdif.D[18]
  lcdif.D[19]
  lcdif.D[20]
  lcdif.D[21]
  lcdif.D[22]
  lcdif.D[23]
- spi6.PCS0
  spi6.SIN
  spi6.SOUT
  spi6.SCK
  spi7.PCS0
  spi7.SIN
  spi7.SOUT
  spi7.SCK
  tpm6.CH0
  tpm3.EXTCLK
  tpm4.EXTCLK
  tpm5.EXTCLK
  spi8.PCS0
  spi8.SIN
  spi8.SOUT
  spi8.SCK
  uart3.CTS_B
  uart3.RTS_B
  spi5.PCS0
  spi5.SIN
  spi5.SOUT
  spi5.SCK
  tpm5.CH1
  tpm6.CH1
  tpm3.CH3
  tpm4.CH3
  tpm5.CH3
  tpm6.CH3
- uart5.TX
  uart5.RX
  uart5.CTS_B
  uart5.RTS_B
  uart6.TX
  uart6.RX
  uart6.CTS_B
  uart6.RTS_B
  uart7.TX
  uart7.RX
  uart7.CTS_B
  uart7.RTS_B
  uart8.TX
  uart8.RX
  uart8.CTS_B
  uart8.RTS_B
  spi4.PCS2
  spi4.PCS1
  spi4.PCS0
  spi4.SIN
  spi4.SOUT
  spi4.SCK
  tpm6.EXTCLK
  dap.TDO_SWO
  dap.TCLK_SWCLK
  dap.TDI
  dap.TMS_SWDIO
- i2c5.SDA
  i2c5.SCL
  i2c6.SDA
  i2c6.SCL
  i2c6.SDA
  i2c6.SCL
  i2c7.SDA
  i2c7.SCL
  i2c7.SDA
  i2c7.SCL
  i2c8.SDA
  i2c8.SCL
  i2c8.SDA
  i2c8.SCL
  uart4.TX
  uart4.RX
  uart4.CTS_B
  uart4.RTS_B
  tpm5.CH2
  tpm6.CH2
  tpm3.CH1
  tpm4.CH1
  i2c5.SDA
  i2c5.SCL
  spi6.PCS1
  spi7.PCS1
  spi8.PCS1
  spi5.PCS1
- sai3.RX_SYNC
  sai3.TX_DATA[0]
  sai3.RX_BCLK
  sai3.TX_SYNC
- GPIO2_I2C4.SDA
- GPIO3_I2C4.SCL
- GPIO4_PDM.CLK
- GPIO14_UART3.TX
- GPIO15_UART3.RX
- GPIO17_SAI3_MCLK
- GPIO27_PUSHBUTTON_INT
- GPIO18_SAI3.RXBCLK
- GPIO22_SPDIF_IN
- GPIO23_SPDIF_OUT
- GPIO24_DC_INT
- GPIO10_SPI3.SOUT
- GPIO9_SPI3.SIN
- GPIO25_DC_RESET
- GPIO11_SPI3.SCK
- GPIO8_SPI3.CS0
- GPIO00_MIC_MUTE_INT
- DC_GPIO1
- GPIO7_SPI3.CS1
- GPIO05_PDM_BITSTREAM_0
- GPIO06_PDM_BITSTREAM_1
- GPIO12_PDM_BITSTREAM2
- GPIO13_PDM_BITSTREAM_3
- GPIO19_SAI3.RXSYNC
- GPIO20_SAI3.RXDATA0
- GPIO21_SAI3.TXDATA0
- Green for Audio-Hat board
- SAI3 TX/RX Selection
- TX CLK/SYNC
- SAI3.TXBCLK
- SAI3.TXSYNC
- SEL=H:   Dx->SxB
- SAI3.RXBCLK
- SEL=L:   Dx->SxA
- SAI3.RXSYNC
- RX CLK/SYNC
- EN=H:   Disable
- EN=L:   Enable
- I.MX91 9x9 package doesn't have TX_SYNC on GPIO_IO pads, need to use TX_SYNC from  other
  pads like UART2_TXD, or use RX_SYNC(GPIO_IO19) with RX_BCLK(GPIO_IO18) instead.
- EXP Power
- TAMPER
- 3.3V@2.5A
- RGB LED w/ PWM
- 5V@2.5A
- I2C CN
- ADC x2 CH
- Buttons
- # Prevent PWR SEQ violation from ADC port
sheet 24
- FLASH: 16GB eMMC 5.1
- QSPI Flash on SDHC3
- NOTE:
- All the CAPs in this page need to be put on the bottom of BGA,
  and close the PINs as short as possible.
- Supported Flash Devices on WSON8X6:
- QSPI NOR:
  -  MT25QU512ABB8E12-0AAT  512Mb   Micron
  -  W25Q512JVEIQ                      512Mb  Winbond
  QSPI NAND:
  -  GD5F2GM7REYIG                  2Gb  GigaDevice
  -  W25N02KWZIER                   2Gb  Winbond
- Close to CPU.
- GND test points should be put closely to signal test points.
- GND test points should be put closely to signal test points.
- OE
- A
- Y
- NOTE
- H
- H
- H
- Normal Operation, card plug-out
- H
- L
- L
- Normal Operation, card insert
- L
- X
- H
- Simulation, card plug-out
- MicroSD 3.0
- Only for simulating SD card Plug-in/out, Remove these
  circuits and install R217/R238 if test not required.
- FT_SD_CD_EN->Low, FT_SD_PWR_EN ->Low   Plug Out
  FT_SD_PWR_EN ->High, FT_SD_CD_EN->High, Plug In
- # Push-Push
- GND test points should be put closely to signal test points.
